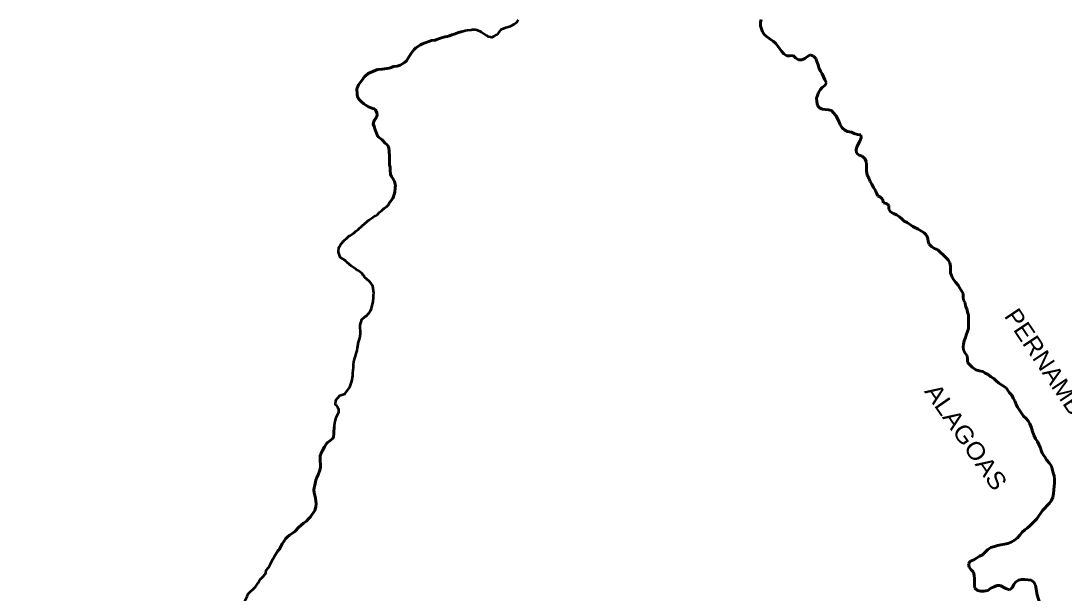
# Model space of a CAD drawing. Extents: x -1643653 to 4543381, y 1624270 to 13878484.
# Drawn here: x 621120 to 644975, y 9005760 to 9018855 of the extents above; entities that cross this region are included whole.
import ezdxf
from ezdxf.enums import TextEntityAlignment as Align

# ---------------------------------------------------------------- set-up
doc = ezdxf.new("R2010")
doc.units = 0
doc.header["$LTSCALE"] = 200
doc.linetypes.add('LONG_DASH_SHORT_DASH', pattern=[9.9, 6, -1.2, 1.5, -1.2])
for name, color, linetype, lineweight in [('24', 7, 'Continuous', 25), ('60', 7, 'Continuous', 13), ('7', 7, 'LONG_DASH_SHORT_DASH', 60)]:
    doc.layers.add(name, color=color, linetype=linetype, lineweight=lineweight)
doc.layers.add('42', color=7, linetype='Continuous')

msp = doc.modelspace()

# ---------------------------------------------------------------- linework, layer by layer
at = {"layer": '24', "lineweight": 53}
for points in [[(629274, 9017743.2), (629381.1, 9017748.3), (629434.5, 9017760.7), (629491.4, 9017765.6), (629537.5, 9017774.2), (629587.5, 9017786.6), (629642.2, 9017809.3), (629725.7, 9017821.8), (629743.8, 9017822.8), (629796.4, 9017840), (629846.5, 9017871.2), (629893.4, 9017902.3), (629935.3, 9017943.9), (629996.6, 9018037.2), (630048.9, 9018124.8), (630080.8, 9018160.6), (630113.1, 9018202.1), (630151.6, 9018240.8), (630254.2, 9018309.8), (630305.7, 9018332.6), (630507.3, 9018408.5), (630590.6, 9018415.3), (630611.9, 9018419.1), (630717.8, 9018458.1), (630816.3, 9018489.4), (630866, 9018499), (630920.7, 9018516.1), (630972.3, 9018535.1), (631025.1, 9018549.3), (631125.3, 9018586.4), (631186.5, 9018602.6), (631229.7, 9018616.8), (631281.3, 9018635.8), (631332.9, 9018645.4), (631418, 9018652.2), (631437.6, 9018655.1), (631504.9, 9018655.3), (631536.1, 9018652.6), (631547.1, 9018648.9), (631646.7, 9018604.1), (631758.6, 9018530.1), (631768.7, 9018519.8), (631780.5, 9018518), (631784.5, 9018507.7), (631788.3, 9018504.8), (631892.4, 9018481.7), (631899.2, 9018482.7), (631945.5, 9018503.5), (631993.7, 9018532.8), (632034.4, 9018569.6), (632106.5, 9018663.9), (632156.3, 9018682.9), (632209.2, 9018700), (632259.2, 9018719), (632312.1, 9018732.3), (632399.5, 9018775.8), (632439.6, 9018808.9), (632466.2, 9018835.3), (632501.5, 9018878.7)], [(629194.7, 9016439.5), (629177.5, 9016494.9), (629187.5, 9016554.2), (629195.7, 9016563.6), (629200.5, 9016575.9), (629237.2, 9016624), (629245.2, 9016644.7), (629258.9, 9016658.8), (629261.5, 9016665.4), (629266.8, 9016705.9), (629260.6, 9016749.1), (629228.6, 9016818.6), (629200.8, 9016838.3), (629166.7, 9016852.3), (629065.4, 9016888.6), (629008.7, 9016922.3), (628959.7, 9016958.8), (628908.5, 9017002.8), (628868.8, 9017038.4), (628831.3, 9017088.2), (628817.9, 9017127.6), (628811.2, 9017173.7), (628801.7, 9017305.3), (628806.4, 9017311.9), (628840.5, 9017391), (628865.1, 9017422.1), (628888.6, 9017455.1), (628938, 9017517.3), (628963.8, 9017556), (628982.6, 9017573), (628987.4, 9017593.7), (629000, 9017599.4), (629064.4, 9017648.5), (629274, 9017743.2)], [(628385.1, 9013563.7), (628384.6, 9013589.1), (628393.8, 9013653.1), (628406.8, 9013693.5), (628435.3, 9013742.5), (628473.3, 9013786.9), (628489.7, 9013813.2), (628501.5, 9013824.6), (628538.5, 9013852.9), (628556, 9013869.9), (628589.9, 9013894.5), (628628.8, 9013933.2), (628651.1, 9013946.4), (628673.7, 9013962.5), (628695.1, 9013973.8), (628729.5, 9013996.5), (628744.7, 9014007.8), (628779.8, 9014042.7), (628830.1, 9014083.3), (628852.5, 9014106), (628910.2, 9014151.3), (628933.9, 9014174), (629083.1, 9014298.6), (629109.7, 9014314.7), (629174, 9014361), (629226.4, 9014394.1), (629271.5, 9014426.2), (629294, 9014445.1), (629316.4, 9014466.8), (629374.3, 9014513.1), (629388, 9014530), (629412.2, 9014553.6), (629427.9, 9014564), (629444.5, 9014579.1), (629470.7, 9014596.1), (629485.8, 9014608.4), (629530.1, 9014656.5), (629544.5, 9014677.3), (629557.5, 9014702.7), (629568.8, 9014719.7), (629611.6, 9014775.3), (629622.1, 9014794.1), (629637.4, 9014828), (629647.2, 9014866.6), (629660.2, 9014906.2), (629668.7, 9014940.1), (629681.7, 9015019.1), (629682.1, 9015052), (629684.7, 9015087.8), (629681.2, 9015117.8), (629661.9, 9015180.8), (629623.3, 9015244.6), (629598, 9015294.4), (629587.7, 9015308.5), (629574.6, 9015342.3), (629564.7, 9015437.2), (629564.2, 9015501.2), (629551.4, 9015566), (629550.9, 9015690.2), (629547.7, 9015731.5), (629550.5, 9015763.5), (629550.4, 9015794.6), (629544.2, 9015827.5), (629543.7, 9015859.4), (629537.5, 9015892.3), (629533.8, 9015933.7), (629524.4, 9015973.2), (629518.3, 9015976.9), (629516.5, 9015989.1), (629490.5, 9016027.6), (629451.9, 9016059.4), (629382.5, 9016129.8), (629285.4, 9016211.2), (629251.8, 9016287.3)], [(629251.8, 9016287.3), (629218.1, 9016364.3), (629194.7, 9016439.5)], [(628991.5, 9012087.3), (629022.5, 9012108.1), (629071.7, 9012160), (629084.9, 9012162.8), (629086.9, 9012173.2), (629118.1, 9012217.5), (629138.3, 9012273), (629162, 9012369), (629172, 9012423.6), (629184.2, 9012523.3), (629184.4, 9012576), (629190.2, 9012625.9), (629183.6, 9012680.4), (629167.1, 9012786.6), (629159.2, 9012796.9), (629128.4, 9012844.8), (629090.7, 9012887.9), (628980.3, 9012992.9), (628979, 9013000.4), (628970.9, 9013002.3), (628969.2, 9013017.3), (628950.2, 9013031.4), (628929.8, 9013068.9), (628829.8, 9013142.9), (628780.7, 9013176.6), (628727.8, 9013209.3), (628680.6, 9013243), (628636, 9013283.3), (628574.8, 9013335.8), (628552.3, 9013351.7), (628548.7, 9013360.1), (628427, 9013439.7), (628422.5, 9013448.1), (628385.1, 9013563.7)], [(626725, 9006288.4), (626779.1, 9006348.8), (626820, 9006414.7), (626852.1, 9006473.1), (626884.2, 9006537.2), (626914.5, 9006591.8), (626995.8, 9006730.4), (627000.8, 9006736), (627018.2, 9006741.7), (627022, 9006744.6), (627030, 9006769), (627091.7, 9006889.6), (627130.8, 9006942.4), (627168.5, 9006999), (627205.7, 9007042.3), (627264.5, 9007088.6), (627330, 9007129.3), (627383.4, 9007169.9), (627473.6, 9007266.1), (627521.8, 9007311.4), (627580.8, 9007360.5), (627647.4, 9007407.8), (627691, 9007452.1), (627741.2, 9007505), (627838.2, 9007649.2), (627862.8, 9007736.7), (627868.9, 9007802.6), (627855.6, 9007930.4), (627843.1, 9007991.5), (627825.9, 9008062.9), (627820.1, 9008114.6), (627823, 9008171.1), (627839.1, 9008232.2), (627861.6, 9008347.1), (627883.5, 9008403.6), (627919.6, 9008464.8), (627956.3, 9008575), (627969.5, 9008644.6), (627969.3, 9008703.9), (627962.7, 9008772.5), (627963, 9008898.5), (627984.8, 9008964.4), (628013.5, 9009025.6), (628060.6, 9009104.8), (628119, 9009194.3), (628125.3, 9009200.9), (628181.5, 9009242.5), (628249.4, 9009298.2), (628267.2, 9009335.9), (628279.4, 9009398.9), (628279.5, 9009462.9), (628282.4, 9009525), (628295.3, 9009656.7), (628310.9, 9009719.8), (628332.7, 9009781.9), (628390, 9009900.6), (628393.8, 9009911.9), (628393.7, 9009960.8), (628392.5, 9009967.4), (628378, 9009983.3), (628365.8, 9010017.1), (628342.8, 9010045.3), (628316.9, 9010072.4), (628323, 9010177.8), (628415.6, 9010283.4), (628526.3, 9010323.3), (628535.7, 9010328), (628642.2, 9010476), (628665.7, 9010541), (628685.1, 9010606.9), (628709.8, 9010732.1), (628710.2, 9010799.8), (628722.3, 9010925.8), (628722.4, 9010990.7), (628731.8, 9011054.7), (628747.3, 9011116.8), (628773, 9011182.8), (628789.2, 9011246.8), (628807.6, 9011309.8), (628814.8, 9011376.6), (628839.2, 9011499.9), (628862, 9011567.7), (628878.5, 9011635.5), (628887.4, 9011699.5), (628887.1, 9011760.6), (628880.7, 9011826.4), (628881.1, 9011890.3), (628917.2, 9012018.4), (628991.5, 9012087.3)], [(626161, 9005249.2), (626188.6, 9005351.8), (626211.6, 9005488.2), (626262, 9005622), (626290.8, 9005686), (626318.1, 9005740.6), (626357.2, 9005784), (626440.5, 9005861.4), (626481.1, 9005905.8), (626516.3, 9005951), (626547.5, 9005998.1), (626576.5, 9006046.2), (626606.6, 9006087.7), (626651.3, 9006133.9), (626697.2, 9006185.8), (626721.1, 9006227.2), (626725, 9006288.4)]]:
    msp.add_lwpolyline(points, dxfattribs=at)
at = {"layer": '60', "lineweight": 25}
msp.add_spline([(814781, 9009175.5), (814787.2, 9009173.4), (814796.9, 9009173.4), (814799.4, 9009172.4), (814805.1, 9009174.5), (814805.6, 9009176.5), (814811.7, 9009179.5), (814811.7, 9009179.5), (814801.5, 9009181), (814790.7, 9009181.5), (814784.1, 9009183.1), (814777.4, 9009185.1), (814778.4, 9009175.5)], degree=3, dxfattribs=at)
at = {"layer": '7'}
for points in [[(638704.2, 9018056.3), (638636.4, 9018051), (638565.9, 9018103.4), (638512.9, 9018158.4), (638467.5, 9018221), (638429.6, 9018278.6), (638384.1, 9018333.6), (638318.6, 9018391.1), (638250.6, 9018436), (638195.2, 9018478.4), (638127.1, 9018538.4), (638081.6, 9018601), (638030.9, 9018738.8), (638035.6, 9018816.7), (638045.4, 9018887)], [(629274, 9017743.2), (629381.1, 9017748.3), (629434.5, 9017760.7), (629491.4, 9017765.6), (629537.5, 9017774.2), (629587.5, 9017786.6), (629642.2, 9017809.3), (629725.7, 9017821.8), (629743.8, 9017822.8), (629796.4, 9017840), (629846.5, 9017871.2), (629893.4, 9017902.3), (629935.3, 9017943.9), (629996.6, 9018037.2), (630048.9, 9018124.8), (630080.8, 9018160.6), (630113.1, 9018202.1), (630151.6, 9018240.8), (630254.2, 9018309.8), (630305.7, 9018332.6), (630507.3, 9018408.5), (630590.6, 9018415.3), (630611.9, 9018419.1), (630717.8, 9018458.1), (630816.3, 9018489.4), (630866, 9018499), (630920.7, 9018516.1), (630972.3, 9018535.1), (631025.1, 9018549.3), (631125.3, 9018586.4), (631186.5, 9018602.6), (631213.4, 9018611.4)], [(639653.5, 9016800.1), (639585.6, 9016819.9), (639510.2, 9016829.6), (639439.8, 9016831.8), (639379.4, 9016866.7), (639339, 9016921.8), (639318.6, 9017007.1), (639315.8, 9017084.9), (639335.7, 9017150.2), (639360.6, 9017215.6), (639393, 9017276), (639445.6, 9017326.4), (639505.7, 9017374.4), (639538.1, 9017437.3), (639502.7, 9017502.4), (639469.8, 9017575.1), (639444.4, 9017645.2), (639401.5, 9017705.3), (639368.5, 9017778), (639348.2, 9017850.7), (639317.8, 9017925.9), (639297.4, 9017996.1), (639247, 9018043.6), (639169, 9018075.9), (639103.8, 9018040.5), (639046.1, 9017997.5), (638980.9, 9017962.1), (638900.5, 9017964.3), (638835.1, 9018006.7), (638779.6, 9018059.2), (638704.2, 9018056.3)], [(629194.7, 9016439.5), (629177.5, 9016494.9), (629187.5, 9016554.2), (629195.7, 9016563.6), (629200.5, 9016575.9), (629237.2, 9016624), (629245.2, 9016644.7), (629258.9, 9016658.8), (629261.5, 9016665.4), (629266.8, 9016705.9), (629260.6, 9016749.1), (629228.6, 9016818.6), (629200.8, 9016838.3), (629166.7, 9016852.3), (629065.4, 9016888.6), (629008.7, 9016922.3), (628959.7, 9016958.8), (628908.5, 9017002.8), (628868.8, 9017038.4), (628831.3, 9017088.2), (628817.9, 9017127.6), (628811.2, 9017173.7), (628801.7, 9017305.3), (628806.4, 9017311.9), (628840.5, 9017391), (628865.1, 9017422.1), (628888.6, 9017455.1), (628938, 9017517.3), (628963.8, 9017556), (628982.6, 9017573), (628987.4, 9017593.7), (629000, 9017599.4), (629064.4, 9017648.5), (629274, 9017743.2)], [(642587.9, 9012738.2), (642555, 9012803.3), (642491.9, 9012875.8), (642449, 9012935.9), (642411, 9013003.5), (642378, 9013091.2), (642377.5, 9013241.9), (642359.6, 9013319.6), (642321.7, 9013387.2), (642261.2, 9013447.2), (642084.7, 9013614.7), (642014.2, 9013649.5), (641953.8, 9013686.9), (641888.2, 9013741.9), (641865.4, 9013807), (641855.1, 9013874.8), (641829.7, 9013952.5), (641771.7, 9014002.5), (641713.8, 9014044.9), (641640.8, 9014087.2), (641512.4, 9014146.9), (641383.9, 9014239.3), (641316, 9014271.6), (641260.5, 9014321.6), (641210.1, 9014371.6), (641144.6, 9014416.5), (641071.7, 9014443.8), (641003.7, 9014483.7), (640965.8, 9014543.8), (640965.5, 9014626.6), (640912.5, 9014674.1), (640844.6, 9014691.4), (640824.2, 9014771.6), (640776.3, 9014821.6), (640713.4, 9014849), (640683, 9014911.6), (640660.2, 9014976.8), (640614.7, 9015039.3), (640579.2, 9015117), (640541.3, 9015177.1), (640508.4, 9015254.8), (640472.9, 9015332.5), (640455.1, 9015415.2), (640454.5, 9015560.8), (640451.7, 9015636.1), (640416.3, 9015703.8), (640355.8, 9015758.8), (640287.9, 9015781.1), (640227.4, 9015828.5), (640219.6, 9015903.8), (640236.9, 9015971.6), (640304.3, 9016102.5), (640336.7, 9016177.9), (640326.4, 9016245.7), (640251, 9016257.9), (640175.5, 9016277.7), (640112.6, 9016305), (640024.6, 9016322.2), (639961.7, 9016357.1), (639898.7, 9016409.5), (639855.7, 9016474.6), (639827.8, 9016547.3), (639754.4, 9016687.6), (639704, 9016747.6), (639653.5, 9016800.1)], [(629251.8, 9016287.3), (629218.1, 9016364.3), (629194.7, 9016439.5)], [(629568.8, 9014719.7), (629611.6, 9014775.3), (629622.1, 9014794.1), (629637.4, 9014828), (629647.2, 9014866.6), (629660.2, 9014906.2), (629668.7, 9014940.1), (629681.7, 9015019.1), (629682.1, 9015052), (629684.7, 9015087.8), (629681.2, 9015117.8), (629661.9, 9015180.8), (629623.3, 9015244.6), (629598, 9015294.4), (629587.7, 9015308.5), (629574.6, 9015342.3), (629564.7, 9015437.2), (629564.2, 9015501.2), (629551.4, 9015566), (629550.9, 9015690.2), (629547.7, 9015731.5), (629550.5, 9015763.5), (629550.4, 9015794.6), (629544.2, 9015827.5), (629543.7, 9015859.4), (629537.5, 9015892.3), (629533.8, 9015933.7), (629524.4, 9015973.2), (629518.3, 9015976.9), (629516.5, 9015989.1), (629490.5, 9016027.6), (629451.9, 9016059.4), (629382.5, 9016129.8), (629285.4, 9016211.2), (629251.8, 9016287.3)], [(642956.5, 9010871.9), (642875.9, 9010931.8), (642812.9, 9010989.2), (642767.5, 9011046.8), (642764.7, 9011117.1), (642756.9, 9011189.8), (642714, 9011252.4), (642671, 9011320), (642668.2, 9011392.8), (642675.5, 9011460.6), (642692.8, 9011531), (642720.2, 9011611.5), (642740, 9011684.4), (642767.4, 9011749.8), (642787.2, 9011815.1), (642792, 9011885.4), (642791.1, 9012118.9), (642768.3, 9012191.6), (642750.4, 9012266.9), (642720, 9012329.5), (642709.7, 9012402.3), (642674.3, 9012462.4), (642669, 9012537.7), (642668.7, 9012615.5), (642587.9, 9012738.2)], [(642909.8, 9006525.4), (642972.5, 9006563.4), (643042.7, 9006603.9), (643110.4, 9006636.8), (643173, 9006699.9), (643233.1, 9006755.4), (643300.8, 9006800.9), (643383.6, 9006828.9), (643451.3, 9006846.8), (643689.8, 9006898), (643767.6, 9006926), (643840.3, 9006969), (643907.9, 9007024.6), (643960.5, 9007085.1), (644013, 9007153.1), (644073.1, 9007208.6), (644128.2, 9007249), (644188.3, 9007299.5), (644348.5, 9007460.9), (644480.9, 9007652.3), (644638.6, 9007816.2), (644681, 9007874.2), (644715.9, 9007949.6), (644735.7, 9008040.1), (644740.4, 9008123), (644752.4, 9008281.2), (644752, 9008371.6), (644749.2, 9008446.9), (644726.4, 9008512.1), (644706.1, 9008577.3), (644685.6, 9008662.5), (644630.1, 9008742.6), (644574.6, 9008810.2), (644531.6, 9008875.3), (644478.6, 9008945.3), (644453.2, 9009020.6), (644432.8, 9009088.2), (644394.9, 9009160.9), (644364.5, 9009226), (644319, 9009288.6), (644283.6, 9009373.8), (644253.1, 9009461.5), (644230.2, 9009539.3), (644192.1, 9009634.5), (644149.2, 9009702.1), (644098.7, 9009762.2), (644045.8, 9009812.1), (643997.8, 9009874.7), (643906.8, 9010017.4), (643876.5, 9010080), (643846, 9010160.2), (643810.6, 9010220.3), (643780.2, 9010290.5), (643729.8, 9010343), (643646.4, 9010458.1), (643563.3, 9010510.5), (643485.3, 9010562.9), (643417.2, 9010627.8), (643364.3, 9010672.8), (643296.3, 9010710.2), (643238.3, 9010762.6), (643170.4, 9010790), (643112.5, 9010829.9), (643034.5, 9010844.6), (642956.5, 9010871.9)], [(626960, 9006669.3), (626995.8, 9006730.4), (627000.8, 9006736), (627018.2, 9006741.7), (627022, 9006744.6), (627030, 9006769), (627091.7, 9006889.6), (627130.8, 9006942.4), (627168.5, 9006999), (627205.7, 9007042.3), (627264.5, 9007088.6), (627330, 9007129.3), (627383.4, 9007169.9), (627473.6, 9007266.1), (627521.8, 9007311.4), (627580.8, 9007360.5), (627647.4, 9007407.8), (627691, 9007452.1), (627741.2, 9007505), (627838.2, 9007649.2), (627862.8, 9007736.7), (627868.9, 9007802.6), (627855.6, 9007930.4), (627843.1, 9007991.5), (627825.9, 9008062.9), (627820.1, 9008114.6), (627823, 9008171.1), (627839.1, 9008232.2), (627861.6, 9008347.1), (627883.5, 9008403.6), (627919.6, 9008464.8), (627956.3, 9008575), (627969.5, 9008644.6), (627969.3, 9008703.9), (627962.7, 9008772.5), (627963, 9008898.5), (627984.8, 9008964.4), (628013.5, 9009025.6), (628060.6, 9009104.8), (628119, 9009194.3), (628125.3, 9009200.9), (628181.5, 9009242.5), (628249.4, 9009298.2), (628267.2, 9009335.9), (628279.4, 9009398.9), (628279.5, 9009462.9), (628282.4, 9009525), (628286.6, 9009568.2)], [(644220.5, 9006056.8), (644074.8, 9006071.2), (644001.9, 9006068.3), (643934.1, 9006053), (643864, 9006012.5), (643821.4, 9005959.6), (643789.1, 9005879.1), (643726.4, 9005838.6), (643645.9, 9005865.8), (643512.5, 9005935.6), (643434.6, 9005937.7), (643374.4, 9005902.3), (643301.7, 9005876.9), (643231.5, 9005821.3), (643141.2, 9005805.8), (643070.8, 9005805.5), (642992.8, 9005822.7), (642932.4, 9005870.2), (642927.1, 9005938), (642924.3, 9006023.3), (642924, 9006093.6), (642921.2, 9006161.4), (642900.9, 9006239.2), (642847.9, 9006296.7), (642805, 9006354.2), (642787.1, 9006434.5), (642834.6, 9006492.5), (642909.8, 9006525.4)], [(645057.4, 9005307.2), (644911.9, 9005243.8), (644769.1, 9005152.8), (644701.4, 9005117.3), (644621.1, 9005096.9), (644548.2, 9005094), (644465.3, 9005103.7), (644409.8, 9005143.6), (644412.1, 9005221.5), (644464.7, 9005269.4), (644479.5, 9005342.3), (644479.2, 9005417.6), (644458.8, 9005497.9), (644408.2, 9005575.5), (644377.8, 9005648.2), (644360, 9005720.9), (644342.1, 9005803.7), (644318.9, 9005944.2), (644281, 9006014.3), (644220.5, 9006056.8)]]:
    msp.add_lwpolyline(points, dxfattribs=at)

# ---------------------------------------------------------------- texts
at = {"layer": '42'}
for s, rotation, width, p in [('PERNAMBUCO', 303.725, 1.05, (644707.5, 9010428)), ('ALAGOAS', 304.834, 1.1, (642567.7, 9009221.7))]:
    msp.add_text(s, height=400, rotation=rotation, dxfattribs=dict(at, width=width)).set_placement(p, align=Align.CENTER)

doc.saveas('drawing.dxf')
